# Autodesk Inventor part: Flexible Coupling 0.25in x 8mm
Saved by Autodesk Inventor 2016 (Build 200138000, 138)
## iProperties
Created: 2016-03
Part Number: Flexible Coupling 0.25in x 8mm
Material: Generic
Document SubType Name: Modeling
Designer: bongo_000
Density: 1 g/cm^3
Appearance: Default
Author: bongo_000
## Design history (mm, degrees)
feature "CHAMFER1"
body "Solid1"
